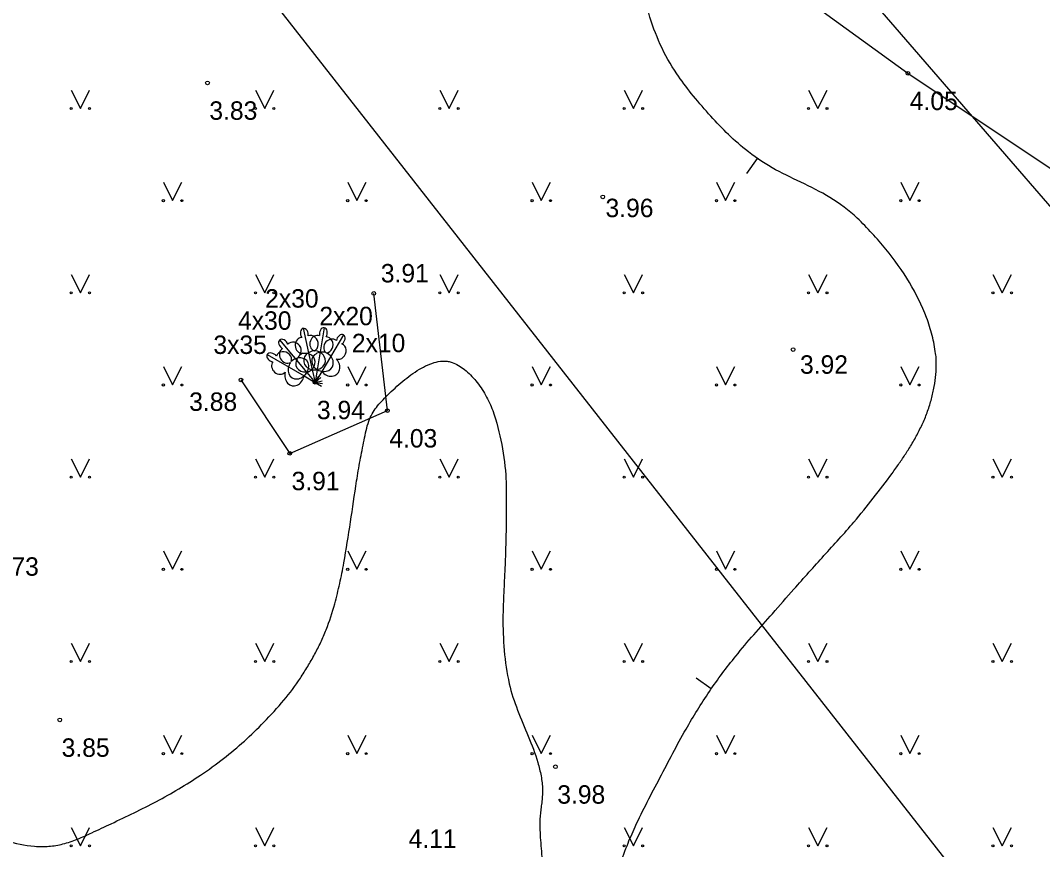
# Model space of a CAD drawing. Extents: x 519536 to 519949, y 326041 to 326519.
# Drawn here: x 519663.37 to 519691.1, y 326234.9 to 326257.39 of the extents above; entities that cross this region are included whole.
import ezdxf

# ---------------------------------------------------------------- set-up
doc = ezdxf.new("R2010")
doc.units = 0
for name, color, linetype in [('APGR_SARK_####_####_#', 7, 'Continuous'), ('CELI_CMAL_####_####_#', 7, 'Continuous'), ('RELJ_AATZ_####_TKST_#', 7, 'Continuous'), ('RELJ_ELEM_####_####_#', 7, 'Continuous'), ('RELJ_HORZ_PAMT_####_#', 7, 'Continuous'), ('TERT_DIAM_####_TKST_#', 7, 'Continuous'), ('TERT_ELEM_####_####_#', 7, 'Continuous'), ('TERT_KOKR_####_####_#', 7, 'Continuous'), ('TERT_KONT_####_####_#', 7, 'Continuous'), ('UDTK_VADP_NEDR_####_#', 7, 'Continuous')]:
    doc.layers.add(name, color=color, linetype=linetype)

msp = doc.modelspace()

# ---------------------------------------------------------------- linework, layer by layer
at = {"layer": 'APGR_SARK_####_####_#'}
msp.add_line((519653.048, 326279.838), (519689.266, 326233.596), dxfattribs=at)
at = {"layer": 'CELI_CMAL_####_####_#'}
msp.add_lwpolyline([(519605.677, 326331.668), (519610.92, 326333.105), (519616.129, 326332.665), (519620.364, 326330.155), (519625.703, 326323.249), (519630.177, 326316.904), (519636.619, 326307.816), (519643.433, 326298.472), (519653.124, 326286.257), (519659.909, 326277.672), (519667.012, 326270.993), (519677.041, 326263.497), (519687.445, 326255.957), (519697.945, 326248.955)], dxfattribs=at)
at = {"layer": 'RELJ_ELEM_####_####_#'}
for centre in [(519687.445, 326255.957), (519668.448, 326255.694), (519679.168, 326252.602), (519672.957, 326249.983), (519684.329, 326248.461), (519669.354, 326247.636), (519671.366, 326247.572), (519673.328, 326246.804), (519670.678, 326245.646), (519664.442, 326238.414), (519677.884, 326237.143)]:
    msp.add_circle(centre, 0.05, dxfattribs=at)
at = {"layer": 'RELJ_HORZ_PAMT_####_#'}
for p, q in [((519683.352, 326253.645), (519683.068, 326253.234)), ((519682.111, 326239.259), (519681.701, 326239.544))]:
    msp.add_line(p, q, dxfattribs=at)
for points in [[(519676.173, 326264.145), (519676.072, 326264.108), (519675.55, 326263.898), (519675.04, 326263.675), (519669.54, 326261.245), (519668.137, 326260.697), (519666.719, 326260.197), (519665.314, 326259.638), (519664.624, 326259.302), (519664.283, 326259.114), (519664.115, 326259.015), (519663.947, 326258.911), (519663.536, 326258.613), (519663.161, 326258.271), (519662.824, 326257.887), (519662.524, 326257.464), (519662.027, 326256.546), (519661.678, 326255.578), (519661.109, 326253.495), (519660.834, 326252.456), (519660.682, 326251.95), (519660.515, 326251.458), (519660.376, 326251.053), (519660.244, 326250.645), (519660.111, 326250.239), (519659.965, 326249.838), (519659.812, 326249.515), (519659.631, 326249.205), (519659.444, 326248.894), (519659.278, 326248.565), (519658.947, 326247.746), (519658.664, 326246.912), (519658.236, 326245.218), (519657.995, 326243.514), (519657.945, 326242.666), (519657.942, 326241.828), (519658.055, 326240.814), (519658.334, 326239.815), (519658.765, 326238.828), (519659.034, 326238.338), (519659.335, 326237.851), (519659.776, 326237.247), (519660.252, 326236.738), (519660.79, 326236.293), (519661.091, 326236.086), (519661.416, 326235.884), (519662.189, 326235.463), (519662.975, 326235.145), (519663.759, 326234.988), (519664.146, 326234.988), (519664.527, 326235.05), (519664.92, 326235.182), (519665.312, 326235.355), (519665.837, 326235.6)], [(519681.57, 326255.408), (519681.174, 326255.943), (519680.729, 326256.738), (519680.414, 326257.584), (519679.996, 326259.37), (519679.839, 326260.039)], [(519688.195, 326248.351), (519688.156, 326248.597), (519688.102, 326248.842), (519687.95, 326249.329), (519687.487, 326250.278), (519686.847, 326251.183), (519686.472, 326251.613), (519686.069, 326252.025), (519685.329, 326252.587), (519684.542, 326253.001), (519683.761, 326253.394), (519683.038, 326253.888), (519682.039, 326254.857), (519681.57, 326255.408)], [(519687.013, 326245.097), (519687.12, 326245.247), (519687.298, 326245.505), (519687.47, 326245.769), (519687.562, 326245.919), (519687.649, 326246.072), (519687.731, 326246.228), (519687.81, 326246.386), (519687.884, 326246.545), (519687.949, 326246.708), (519688.007, 326246.873), (519688.06, 326247.042), (519688.142, 326247.372), (519688.196, 326247.707), (519688.214, 326248.034), (519688.212, 326248.192), (519688.206, 326248.272), (519688.195, 326248.351)], [(519669.977, 326238.352), (519670.52, 326238.951), (519670.966, 326239.549), (519671.165, 326239.865), (519671.352, 326240.19), (519671.52, 326240.521), (519671.665, 326240.862), (519671.9, 326241.566), (519671.97, 326241.841), (519672.035, 326242.116), (519672.145, 326242.672), (519672.326, 326243.784), (519672.492, 326244.897), (519672.586, 326245.451), (519672.696, 326246.003), (519672.823, 326246.519), (519673.028, 326246.893), (519673.172, 326247.059), (519673.333, 326247.225), (519673.742, 326247.601), (519674.195, 326247.926), (519674.654, 326248.122), (519674.873, 326248.148), (519674.978, 326248.138), (519675.079, 326248.112), (519675.418, 326247.919), (519675.729, 326247.61), (519675.991, 326247.225), (519676.097, 326247.017), (519676.183, 326246.806), (519676.428, 326245.882), (519676.543, 326244.949), (519676.549, 326244.48), (519676.55, 326244.012), (519676.533, 326243.074), (519676.517, 326242.609), (519676.495, 326242.144), (519676.475, 326241.678), (519676.46, 326241.213), (519676.496, 326240.297), (519676.632, 326239.396), (519676.858, 326238.681), (519677.149, 326237.973), (519677.407, 326237.258), (519677.494, 326236.894), (519677.536, 326236.523), (519677.532, 326236.38), (519677.516, 326236.21), (519677.495, 326236.04), (519677.475, 326235.87), (519677.463, 326235.7), (519677.479, 326235.155), (519677.531, 326234.548), (519677.728, 326233.306), (519677.854, 326232.787), (519677.934, 326232.532), (519678.023, 326232.278), (519678.197, 326231.941), (519678.289, 326231.833), (519678.336, 326231.796), (519678.36, 326231.783), (519678.384, 326231.772), (519678.481, 326231.769), (519678.58, 326231.828), (519678.64, 326231.893), (519678.693, 326231.96), (519678.779, 326232.105), (519678.89, 326232.356), (519678.996, 326232.608), (519679.187, 326233.118), (519679.61, 326234.394), (519679.827, 326235.002), (519680.048, 326235.519), (519680.719, 326236.847), (519681.426, 326238.164), (519682.061, 326239.187), (519682.776, 326240.147), (519683.768, 326241.296)], [(519683.768, 326241.296), (519684.354, 326241.963), (519685.168, 326242.871), (519685.979, 326243.782), (519687.013, 326245.097)], [(519665.837, 326235.6), (519666.457, 326235.897), (519667.067, 326236.206), (519667.667, 326236.543), (519668.262, 326236.92), (519668.881, 326237.369), (519669.447, 326237.842), (519669.977, 326238.352)]]:
    msp.add_spline(points, degree=3, dxfattribs=at)
at = {"layer": 'TERT_ELEM_####_####_#'}
for p, q in [((519664.75, 326255.5), (519665, 326255)), ((519665, 326255), (519665.25, 326255.5)), ((519669.75, 326255.5), (519670, 326255)), ((519670, 326255), (519670.25, 326255.5)), ((519674.75, 326255.5), (519675, 326255)), ((519675, 326255), (519675.25, 326255.5)), ((519679.75, 326255.5), (519680, 326255)), ((519680, 326255), (519680.25, 326255.5)), ((519684.75, 326255.5), (519685, 326255)), ((519685, 326255), (519685.25, 326255.5)), ((519667.25, 326253), (519667.5, 326252.5)), ((519667.5, 326252.5), (519667.75, 326253)), ((519672.25, 326253), (519672.5, 326252.5)), ((519672.5, 326252.5), (519672.75, 326253)), ((519677.25, 326253), (519677.5, 326252.5)), ((519677.5, 326252.5), (519677.75, 326253)), ((519682.25, 326253), (519682.5, 326252.5)), ((519682.5, 326252.5), (519682.75, 326253)), ((519687.25, 326253), (519687.5, 326252.5)), ((519687.5, 326252.5), (519687.75, 326253)), ((519664.75, 326250.5), (519665, 326250)), ((519665, 326250), (519665.25, 326250.5)), ((519669.75, 326250.5), (519670, 326250)), ((519670, 326250), (519670.25, 326250.5)), ((519674.75, 326250.5), (519675, 326250)), ((519675, 326250), (519675.25, 326250.5)), ((519679.75, 326250.5), (519680, 326250)), ((519680, 326250), (519680.25, 326250.5)), ((519684.75, 326250.5), (519685, 326250)), ((519685, 326250), (519685.25, 326250.5)), ((519689.75, 326250.5), (519690, 326250)), ((519690, 326250), (519690.25, 326250.5)), ((519667.25, 326248), (519667.5, 326247.5)), ((519667.5, 326247.5), (519667.75, 326248)), ((519672.25, 326248), (519672.5, 326247.5)), ((519672.5, 326247.5), (519672.75, 326248)), ((519677.25, 326248), (519677.5, 326247.5)), ((519677.5, 326247.5), (519677.75, 326248)), ((519682.25, 326248), (519682.5, 326247.5)), ((519682.5, 326247.5), (519682.75, 326248)), ((519687.25, 326248), (519687.5, 326247.5)), ((519687.5, 326247.5), (519687.75, 326248)), ((519671.066, 326247.746), (519671.366, 326247.572)), ((519671.144, 326247.839), (519671.366, 326247.572)), ((519671.291, 326247.911), (519671.366, 326247.572)), ((519671.423, 326247.914), (519671.366, 326247.572)), ((519671.545, 326247.87), (519671.366, 326247.572)), ((519671.366, 326247.572), (519671.466, 326247.745)), ((519671.366, 326247.572), (519671.519, 326247.7)), ((519671.366, 326247.572), (519671.561, 326247.615)), ((519671.366, 326247.572), (519671.563, 326247.539)), ((519671.366, 326247.572), (519671.537, 326247.469)), ((519664.75, 326245.5), (519665, 326245)), ((519665, 326245), (519665.25, 326245.5)), ((519669.75, 326245.5), (519670, 326245)), ((519670, 326245), (519670.25, 326245.5)), ((519674.75, 326245.5), (519675, 326245)), ((519675, 326245), (519675.25, 326245.5)), ((519679.75, 326245.5), (519680, 326245)), ((519680, 326245), (519680.25, 326245.5)), ((519684.75, 326245.5), (519685, 326245)), ((519685, 326245), (519685.25, 326245.5)), ((519689.75, 326245.5), (519690, 326245)), ((519690, 326245), (519690.25, 326245.5)), ((519667.25, 326243), (519667.5, 326242.5)), ((519667.5, 326242.5), (519667.75, 326243)), ((519672.25, 326243), (519672.5, 326242.5)), ((519672.5, 326242.5), (519672.75, 326243)), ((519677.25, 326243), (519677.5, 326242.5)), ((519677.5, 326242.5), (519677.75, 326243)), ((519682.25, 326243), (519682.5, 326242.5)), ((519682.5, 326242.5), (519682.75, 326243)), ((519687.25, 326243), (519687.5, 326242.5)), ((519687.5, 326242.5), (519687.75, 326243)), ((519664.75, 326240.5), (519665, 326240)), ((519665, 326240), (519665.25, 326240.5)), ((519669.75, 326240.5), (519670, 326240)), ((519670, 326240), (519670.25, 326240.5)), ((519674.75, 326240.5), (519675, 326240)), ((519675, 326240), (519675.25, 326240.5)), ((519679.75, 326240.5), (519680, 326240)), ((519680, 326240), (519680.25, 326240.5)), ((519684.75, 326240.5), (519685, 326240)), ((519685, 326240), (519685.25, 326240.5)), ((519689.75, 326240.5), (519690, 326240)), ((519690, 326240), (519690.25, 326240.5)), ((519667.25, 326238), (519667.5, 326237.5)), ((519667.5, 326237.5), (519667.75, 326238)), ((519672.25, 326238), (519672.5, 326237.5)), ((519672.5, 326237.5), (519672.75, 326238)), ((519677.25, 326238), (519677.5, 326237.5)), ((519677.5, 326237.5), (519677.75, 326238)), ((519682.25, 326238), (519682.5, 326237.5)), ((519682.5, 326237.5), (519682.75, 326238)), ((519687.25, 326238), (519687.5, 326237.5)), ((519687.5, 326237.5), (519687.75, 326238)), ((519664.75, 326235.5), (519665, 326235)), ((519665, 326235), (519665.25, 326235.5)), ((519669.75, 326235.5), (519670, 326235)), ((519670, 326235), (519670.25, 326235.5)), ((519679.75, 326235.5), (519680, 326235)), ((519680, 326235), (519680.25, 326235.5)), ((519684.75, 326235.5), (519685, 326235)), ((519685, 326235), (519685.25, 326235.5)), ((519689.75, 326235.5), (519690, 326235)), ((519690, 326235), (519690.25, 326235.5))]:
    msp.add_line(p, q, dxfattribs=at)
for points in [[(519671.042, 326249.037), (519671.291, 326247.911)], [(519671.18, 326248.829), (519671.179, 326248.83)], [(519671.613, 326249.052), (519671.423, 326247.914)], [(519672.139, 326248.858), (519671.545, 326247.87)], [(519671.663, 326248.808), (519671.663, 326248.809)], [(519670.405, 326248.724), (519671.144, 326247.839)], [(519670.623, 326248.603), (519670.622, 326248.603)], [(519672.096, 326248.612), (519672.095, 326248.614)], [(519670.068, 326248.325), (519671.066, 326247.746)], [(519670.314, 326248.286), (519670.313, 326248.286)]]:
    msp.add_lwpolyline(points, dxfattribs=at)
for centre, radius in [((519664.75, 326255), 0.028), ((519665.25, 326255), 0.0263), ((519669.75, 326255), 0.028), ((519670.25, 326255), 0.0263), ((519674.75, 326255), 0.028), ((519675.25, 326255), 0.0263), ((519679.75, 326255), 0.028), ((519680.25, 326255), 0.0263), ((519684.75, 326255), 0.028), ((519685.25, 326255), 0.0263), ((519667.25, 326252.5), 0.028), ((519667.75, 326252.5), 0.0263), ((519672.25, 326252.5), 0.028), ((519672.75, 326252.5), 0.0263), ((519677.25, 326252.5), 0.028), ((519677.75, 326252.5), 0.0263), ((519682.25, 326252.5), 0.028), ((519682.75, 326252.5), 0.0263), ((519687.25, 326252.5), 0.028), ((519687.75, 326252.5), 0.0263), ((519664.75, 326250), 0.028), ((519665.25, 326250), 0.0263), ((519669.75, 326250), 0.028), ((519670.25, 326250), 0.0263), ((519674.75, 326250), 0.028), ((519675.25, 326250), 0.0263), ((519679.75, 326250), 0.028), ((519680.25, 326250), 0.0263), ((519684.75, 326250), 0.028), ((519685.25, 326250), 0.0263), ((519689.75, 326250), 0.028), ((519690.25, 326250), 0.0263), ((519667.25, 326247.5), 0.028), ((519667.75, 326247.5), 0.0263), ((519672.25, 326247.5), 0.028), ((519672.75, 326247.5), 0.0263), ((519677.25, 326247.5), 0.028), ((519677.75, 326247.5), 0.0263), ((519682.25, 326247.5), 0.028), ((519682.75, 326247.5), 0.0263), ((519687.25, 326247.5), 0.028), ((519687.75, 326247.5), 0.0263), ((519664.75, 326245), 0.028), ((519665.25, 326245), 0.0263), ((519669.75, 326245), 0.028), ((519670.25, 326245), 0.0263), ((519674.75, 326245), 0.028), ((519675.25, 326245), 0.0263), ((519679.75, 326245), 0.028), ((519680.25, 326245), 0.0263), ((519684.75, 326245), 0.028), ((519685.25, 326245), 0.0263), ((519689.75, 326245), 0.028), ((519690.25, 326245), 0.0263), ((519667.25, 326242.5), 0.028), ((519667.75, 326242.5), 0.0263), ((519672.25, 326242.5), 0.028), ((519672.75, 326242.5), 0.0263), ((519677.25, 326242.5), 0.028), ((519677.75, 326242.5), 0.0263), ((519682.25, 326242.5), 0.028), ((519682.75, 326242.5), 0.0263), ((519687.25, 326242.5), 0.028), ((519687.75, 326242.5), 0.0263), ((519664.75, 326240), 0.028), ((519665.25, 326240), 0.0263), ((519669.75, 326240), 0.028), ((519670.25, 326240), 0.0263), ((519674.75, 326240), 0.028), ((519675.25, 326240), 0.0263), ((519679.75, 326240), 0.028), ((519680.25, 326240), 0.0263), ((519684.75, 326240), 0.028), ((519685.25, 326240), 0.0263), ((519689.75, 326240), 0.028), ((519690.25, 326240), 0.0263), ((519667.25, 326237.5), 0.028), ((519667.75, 326237.5), 0.0263), ((519672.25, 326237.5), 0.028), ((519672.75, 326237.5), 0.0263), ((519677.25, 326237.5), 0.028), ((519677.75, 326237.5), 0.0263), ((519682.25, 326237.5), 0.028), ((519682.75, 326237.5), 0.0263), ((519687.25, 326237.5), 0.028), ((519687.75, 326237.5), 0.0263), ((519664.75, 326235), 0.028), ((519665.25, 326235), 0.0263), ((519669.75, 326235), 0.028), ((519670.25, 326235), 0.0263), ((519679.75, 326235), 0.028), ((519680.25, 326235), 0.0263), ((519684.75, 326235), 0.028), ((519685.25, 326235), 0.0263), ((519689.75, 326235), 0.028), ((519690.25, 326235), 0.0263)]:
    msp.add_circle(centre, radius, dxfattribs=at)
for centre, major_axis, ratio, start_param, end_param in [((519671.589, 326248.904), (-0.025, -0.148), 0.707107, 3.14537, 5.287485), ((519671.013, 326248.575), (0.008, -0.216), 0.861323, 3.141593, 6.283185), ((519671.075, 326248.891), (0.032, -0.146), 0.707107, 3.14537, 5.287485), ((519671.074, 326248.89), (0.032, -0.146), 0.707107, 0.995701, 3.137816), ((519671.263, 326248.63), (0.084, -0.199), 0.861323, 0, 3.141593), ((519671.413, 326248.634), (-0.073, -0.203), 0.861323, 3.141593, 6.283185), ((519671.588, 326248.904), (-0.025, -0.148), 0.707107, 0.995701, 3.137816), ((519671.667, 326248.592), (0.003, -0.216), 0.861323, 0, 3.141593), ((519672.062, 326248.729), (-0.077, -0.128), 0.707107, 3.14537, 5.287485), ((519672.061, 326248.729), (-0.077, -0.128), 0.707107, 0.995701, 3.137816), ((519670.502, 326248.609), (0.096, -0.115), 0.707107, 3.14537, 5.287485), ((519670.501, 326248.609), (0.096, -0.115), 0.707107, 0.995701, 3.137816), ((519670.789, 326248.465), (0.166, -0.138), 0.861323, 0, 3.141593), ((519671.8, 326248.543), (-0.143, -0.162), 0.861323, 3.141593, 6.283185), ((519672.019, 326248.41), (-0.076, -0.202), 0.861323, 0, 3.141593), ((519670.198, 326248.25), (0.13, -0.075), 0.707107, 3.14537, 5.287485), ((519670.198, 326248.25), (0.13, -0.075), 0.707107, 0.995701, 3.137816), ((519670.518, 326248.213), (0.203, -0.073), 0.861323, 0, 3.141593), ((519670.592, 326248.301), (0.106, -0.188), 0.861323, 3.141593, 6.283185), ((519670.898, 326247.947), (-0.236, -0.218), 0.814445, 1.531171, 4.712389), ((519671.15, 326248.132), (0.279, 0.159), 0.814445, 1.570796, 4.752015), ((519671.055, 326248.085), (-0.297, -0.123), 0.814445, 1.531171, 4.712389), ((519671.375, 326248.172), (0.318, 0.043), 0.814445, 1.570796, 4.752015), ((519671.595, 326248.126), (0.312, -0.077), 0.814445, 1.570796, 4.752015), ((519671.325, 326248.17), (-0.32, 0.027), 0.814445, 1.531171, 4.712389), ((519671.552, 326248.142), (-0.287, 0.144), 0.814445, 1.531171, 4.712389), ((519670.389, 326247.991), (0.164, -0.14), 0.861323, 3.141593, 6.283185), ((519670.917, 326247.97), (0.175, 0.27), 0.814445, 1.570796, 4.752015), ((519671.748, 326248.034), (-0.214, 0.24), 0.814445, 1.531171, 4.712389), ((519670.808, 326247.792), (0.072, 0.313), 0.814445, 1.570796, 4.752015)]:
    msp.add_ellipse(centre, major_axis=major_axis, ratio=ratio, start_param=start_param, end_param=end_param, dxfattribs=at)
at = {"layer": 'TERT_KOKR_####_####_#'}
msp.add_lwpolyline([(519669.354, 326247.636), (519670.678, 326245.646), (519673.328, 326246.804), (519672.957, 326249.983)], dxfattribs=at)
at = {"layer": 'TERT_KONT_####_####_#'}
msp.add_spline([(519695.425, 326219.384), (519693.978, 326218.661), (519689.122, 326224.89), (519693.466, 326236.184), (519702.773, 326236.749)], degree=3, dxfattribs=at)
at = {"layer": 'UDTK_VADP_NEDR_####_#'}
msp.add_lwpolyline([(519702.552, 326239.356), (519678.816, 326266.783)], dxfattribs=at)

# ---------------------------------------------------------------- texts
at = {"layer": 'RELJ_AATZ_####_TKST_#'}
for s, p in [('4.05', (519687.495, 326254.957)), ('3.83', (519668.498, 326254.694)), ('3.96', (519679.242, 326252.053)), ('3.91', (519673.149, 326250.282)), ('3.92', (519684.518, 326247.805)), ('3.88', (519667.951, 326246.798)), ('3.94', (519671.416, 326246.572)), ('4.03', (519673.378, 326245.804)), ('3.91', (519670.728, 326244.646)), ('3.73', (519662.572, 326242.326)), ('3.85', (519664.492, 326237.414)), ('3.98', (519677.934, 326236.143)), ('4.11', (519673.902, 326234.944))]:
    msp.add_text(s, height=0.5, dxfattribs=at).set_placement(p)
at = {"layer": 'TERT_DIAM_####_TKST_#'}
for s, p in [('2x30', (519670.011, 326249.599)), ('2x20', (519671.482, 326249.121)), ('4x30', (519669.276, 326248.998)), ('3x35', (519668.608, 326248.342)), ('2x10', (519672.363, 326248.39))]:
    msp.add_text(s, height=0.5, dxfattribs=at).set_placement(p)

doc.saveas('drawing.dxf')
